// Mitsubishi GX Works2 project: MotionControl_JEC_FBs_Q   PLC: Q06UDV

TYPE stRemoteRegBasic : STRUCT
  bnRX : ARRAY [0..127] OF BOOL;
  bnRY : ARRAY [0..127] OF BOOL;
  unRWr : ARRAY [0..63] OF WORD;
  unRWw : ARRAY [0..63] OF WORD;
END_STRUCT END_TYPE

// global labels: Global1
VAR_GLOBAL
  Axis1 : AXIS_REF_JEC;
  G_stLinkBasic : stRemoteRegBasic;
  Axis2 : AXIS_REF_JEC;
END_VAR
// user libraries (not included): MotionControl_JEC_V100A

FUNCTION_BLOCK CCIEFBasicStart
VAR_IN_OUT
  Axis : AXIS_REF_JEC;  (* Axis information *)
END_VAR
VAR_INPUT
  Enable : BOOL;  (* Enable *)
END_VAR
VAR_OUTPUT
  Status : BOOL;  (* Normal completion *)
  Error : BOOL;  (* Error completion *)
  ErrorID : WORD;  (* Error code *)
END_VAR
VAR
  bEnablePls : BOOL;
  wAxisNo : INT;
  wRX3F : INT;
  wRY3F : INT;
END_VAR
(*****************************************************************************
 *    <FB NAME>		CCIEFBasicStart
 *   <Description>		CC-Link IEF Basic communication start
 *
 *   COPYRIGHT (C) 2016 MITSUBISHI ELECTRIC CORPORATION ALL RIGHT RESERVED  
 *****************************************************************************)

PLS(Enable, bEnablePls);
IF Enable THEN
	IF bEnablePls THEN
		Status	:= FALSE;
		Error		:= FALSE;
		ErrorID	:= 0;

		(* 入力ラベル範囲チェック *)
		wAxisNo := Axis.AxisNo;
		MOV(((wAxisNo < 1) OR ( 16 < wAxisNo)), H1100, ErrorID);

		IF (ErrorID = 0) THEN
			(* リンクデバイス算出 *)
			wRY3F	:= ((wAxisNo-1) * 64) + H003F;	(* RY(n+3)F:Basic通信指令 *)
			wRX3F	:= ((wAxisNo-1) * 64) + H003F;	(* RX(n+3)F:Basic通信準備完了 *)

			(* Basic通信指令セット *)
			SET(TRUE, G_stLinkBasic.bnRY[wRY3F]);
		END_IF;
	END_IF;
	
	(* 状態出力 *)
	IF (ErrorID = 0) THEN
		Status := G_stLinkBasic.bnRX[wRX3F];
	END_IF;

	Error := (ErrorID <> 0);

ELSE
	bEnablePls	:= FALSE;
	Status		:= FALSE;
	Error			:= FALSE;
	ErrorID		:= 0;
END_IF;
END_FUNCTION_BLOCK

PROGRAM PrgAxis1
VAR
  CCIEFBasicStart_1 : CCIEFBasicStart;
  PowerOn : BOOL;
  Homing : BOOL;
  ExecSpeed : BOOL;
  Velocity : LREAL;
  ExecTorque : BOOL;
  Torque : REAL;
  TorqueRamp : LREAL;
  ExecHalt : BOOL;
  ExecStop : BOOL;
  ReadError : BOOL;
  ExecReset : BOOL;
  ExecAbs : BOOL;
  Position : LREAL;
  ExecInc : BOOL;
  Distance : LREAL;
  ExecAdd : BOOL;
  Monitor : BOOL;
  MonPosition : LREAL;
  MonVelocity : LREAL;
  MonTorque : REAL;
  MC_Power_JEC_1 : MC_Power_JEC;
  MCv_Home_JEC_1 : MCv_Home_JEC;
  MC_MoveVelocity_JEC_1 : MC_MoveVelocity_JEC;
  MC_TorqueControl_JEC_1 : MC_TorqueControl_JEC;
  MC_Halt_JEC_1 : MC_Halt_JEC;
  MC_Stop_JEC_1 : MC_Stop_JEC;
  MC_ReadAxisError_JEC_1 : MC_ReadAxisError_JEC;
  MC_Reset_JEC_1 : MC_Reset_JEC;
  MC_MoveAbsolute_JEC_1 : MC_MoveAbsolute_JEC;
  MC_MoveRelative_JEC_1 : MC_MoveRelative_JEC;
  MC_MoveAdditive_JEC_1 : MC_MoveAdditive_JEC;
  MC_ReadActualPosition_JEC_1 : MC_ReadActualPosition_JEC;
  MC_ReadActualVelocity_JEC_1 : MC_ReadActualVelocity_JEC;
  MC_ReadActualTorque_JEC_1 : MC_ReadActualTorque_JEC;
  MC_ReadAxisInfo_JEC_1 : MC_ReadAxisInfo_JEC;
  MC_ReadStatus_JEC_1 : MC_ReadStatus_JEC;
  BasicStatus : BOOL;
  ErrorCode : WORD;
END_VAR
(* structured ladder/FBD written out as ST: instructions are called as NAME(EN, inputs, outputs); _pN, _eN, _tN stand for wires *)
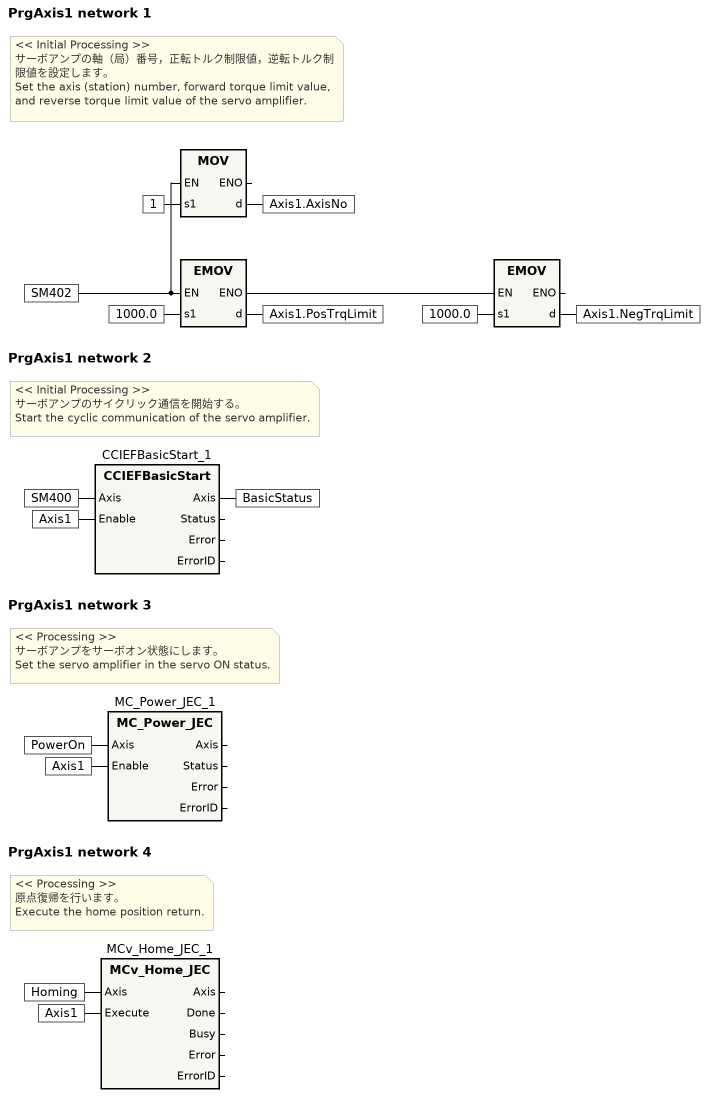
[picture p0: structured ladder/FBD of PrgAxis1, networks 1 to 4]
(* network 1 *)
(* << Initial Processing >> /  / サーボアンプの軸（局）番号，正転トルク制限値，逆転トルク制限値を設定します。 / Set the axis (station) number, forward torque limit value, and reverse torque limit value of the servo amplifier. *)
MOV(SM402, 1, Axis1.AxisNo);
_e1 := EMOV(SM402, 1000.0, Axis1.PosTrqLimit);
EMOV(_e1, 1000.0, Axis1.NegTrqLimit);
(* network 2 *)
(* << Initial Processing >> /  / サーボアンプのサイクリック通信を開始する。 / Start the cyclic communication of the servo amplifier. *)
CCIEFBasicStart_1(Axis := SM400, Enable := Axis1);
BasicStatus := CCIEFBasicStart_1.Axis;
(* network 3 *)
(* << Processing >> /  / サーボアンプをサーボオン状態にします。 / Set the servo amplifier in the servo ON status. *)
MC_Power_JEC_1(Axis := PowerOn, Enable := Axis1);
(* network 4 *)
(* << Processing >> /  / 原点復帰を行います。 / Execute the home position return. *)
MCv_Home_JEC_1(Axis := Homing, Execute := Axis1);
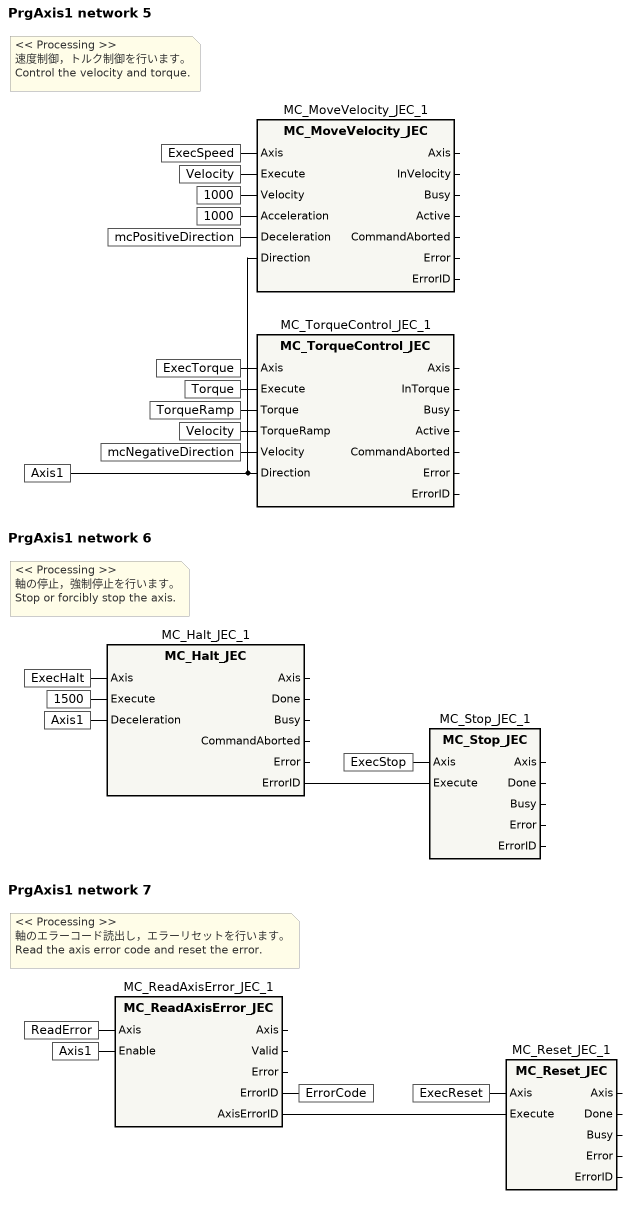
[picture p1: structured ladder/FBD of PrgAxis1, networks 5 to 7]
(* network 5 *)
(* << Processing >> /  / 速度制御，トルク制御を行います。 / Control the velocity and torque. *)
MC_MoveVelocity_JEC_1(Axis := ExecSpeed, Execute := Velocity, Velocity := 1000, Acceleration := 1000, Deceleration := mcPositiveDirection, Direction := Axis1);
MC_TorqueControl_JEC_1(Axis := ExecTorque, Execute := Torque, Torque := TorqueRamp, TorqueRamp := Velocity, Velocity := mcNegativeDirection, Direction := Axis1);
(* network 6 *)
(* << Processing >> /  / 軸の停止，強制停止を行います。 / Stop or forcibly stop the axis. *)
MC_Halt_JEC_1(Axis := ExecHalt, Execute := 1500, Deceleration := Axis1);
MC_Stop_JEC_1(Axis := ExecStop, Execute := MC_Halt_JEC_1.ErrorID);
(* network 7 *)
(* << Processing >> /  / 軸のエラーコード読出し，エラーリセットを行います。 / Read the axis error code and reset the error. *)
MC_ReadAxisError_JEC_1(Axis := ReadError, Enable := Axis1, ErrorID => ErrorCode);
MC_Reset_JEC_1(Axis := ExecReset, Execute := MC_ReadAxisError_JEC_1.AxisErrorID);
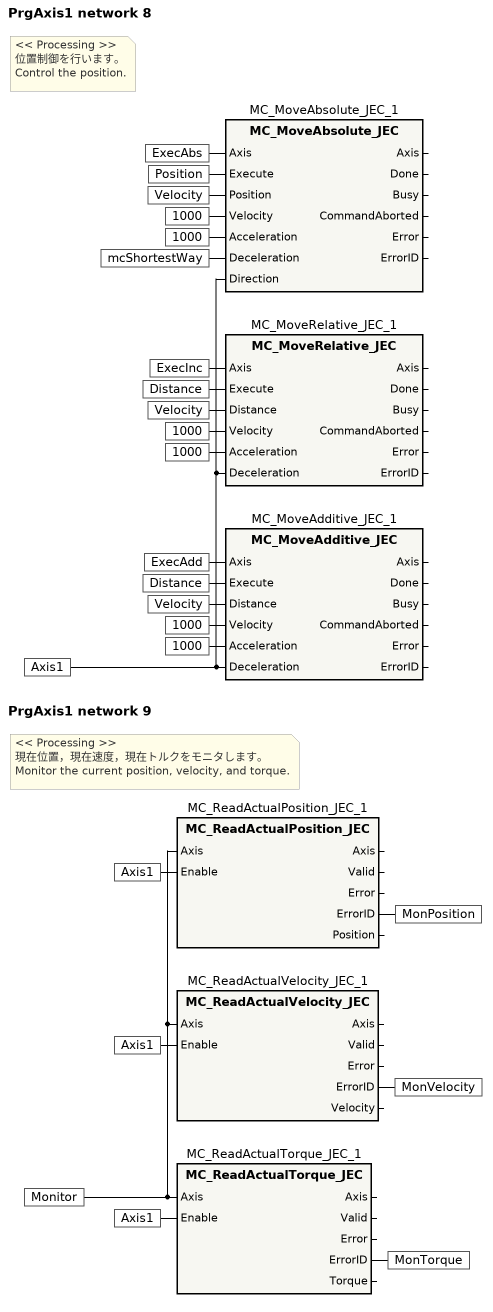
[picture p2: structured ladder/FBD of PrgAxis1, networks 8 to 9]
(* network 8 *)
(* << Processing >> /  / 位置制御を行います。 / Control the position. *)
MC_MoveAbsolute_JEC_1(Axis := ExecAbs, Execute := Position, Position := Velocity, Velocity := 1000, Acceleration := 1000, Deceleration := mcShortestWay, Direction := Axis1);
MC_MoveRelative_JEC_1(Axis := ExecInc, Execute := Distance, Distance := Velocity, Velocity := 1000, Acceleration := 1000, Deceleration := Axis1);
MC_MoveAdditive_JEC_1(Axis := ExecAdd, Execute := Distance, Distance := Velocity, Velocity := 1000, Acceleration := 1000, Deceleration := Axis1);
(* network 9 *)
(* << Processing >> /  / 現在位置，現在速度，現在トルクをモニタします。 / Monitor the current position, velocity, and torque. *)
MC_ReadActualPosition_JEC_1(Axis := Monitor, Enable := Axis1, ErrorID => MonPosition);
MC_ReadActualVelocity_JEC_1(Axis := Monitor, Enable := Axis1, ErrorID => MonVelocity);
MC_ReadActualTorque_JEC_1(Axis := Monitor, Enable := Axis1, ErrorID => MonTorque);
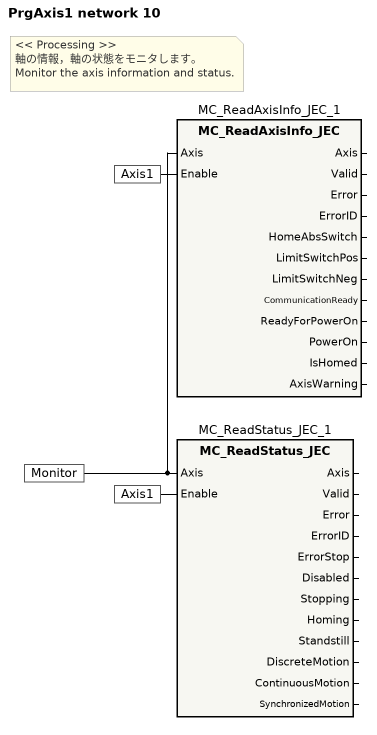
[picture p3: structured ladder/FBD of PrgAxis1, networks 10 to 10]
(* network 10 *)
(* << Processing >> /  / 軸の情報，軸の状態をモニタします。 / Monitor the axis information and status. *)
MC_ReadAxisInfo_JEC_1(Axis := Monitor, Enable := Axis1);
MC_ReadStatus_JEC_1(Axis := Monitor, Enable := Axis1);
END_PROGRAM

PROGRAM PrgAxis2
VAR
  CCIEFBasicStart_1 : CCIEFBasicStart;
  PowerOn : BOOL;
  Homing : BOOL;
  ExecSpeed : BOOL;
  Velocity : LREAL;
  ExecTorque : BOOL;
  Torque : REAL;
  TorqueRamp : LREAL;
  ExecHalt : BOOL;
  ExecStop : BOOL;
  ReadError : BOOL;
  ExecReset : BOOL;
  ExecAbs : BOOL;
  Position : LREAL;
  ExecInc : BOOL;
  Distance : LREAL;
  ExecAdd : BOOL;
  Monitor : BOOL;
  MonPosition : LREAL;
  MonVelocity : LREAL;
  MonTorque : REAL;
  MC_Power_JEC_1 : MC_Power_JEC;
  MCv_Home_JEC_1 : MCv_Home_JEC;
  MC_MoveVelocity_JEC_1 : MC_MoveVelocity_JEC;
  MC_TorqueControl_JEC_1 : MC_TorqueControl_JEC;
  MC_Halt_JEC_1 : MC_Halt_JEC;
  MC_Stop_JEC_1 : MC_Stop_JEC;
  MC_ReadAxisError_JEC_1 : MC_ReadAxisError_JEC;
  MC_Reset_JEC_1 : MC_Reset_JEC;
  MC_MoveAbsolute_JEC_1 : MC_MoveAbsolute_JEC;
  MC_MoveRelative_JEC_1 : MC_MoveRelative_JEC;
  MC_MoveAdditive_JEC_1 : MC_MoveAdditive_JEC;
  MC_ReadActualPosition_JEC_1 : MC_ReadActualPosition_JEC;
  MC_ReadActualVelocity_JEC_1 : MC_ReadActualVelocity_JEC;
  MC_ReadActualTorque_JEC_1 : MC_ReadActualTorque_JEC;
  MC_ReadAxisInfo_JEC_1 : MC_ReadAxisInfo_JEC;
  MC_ReadStatus_JEC_1 : MC_ReadStatus_JEC;
  BasicStatus : BOOL;
  ErrorCode : WORD;
END_VAR
(* structured ladder/FBD written out as ST: instructions are called as NAME(EN, inputs, outputs); _pN, _eN, _tN stand for wires *)
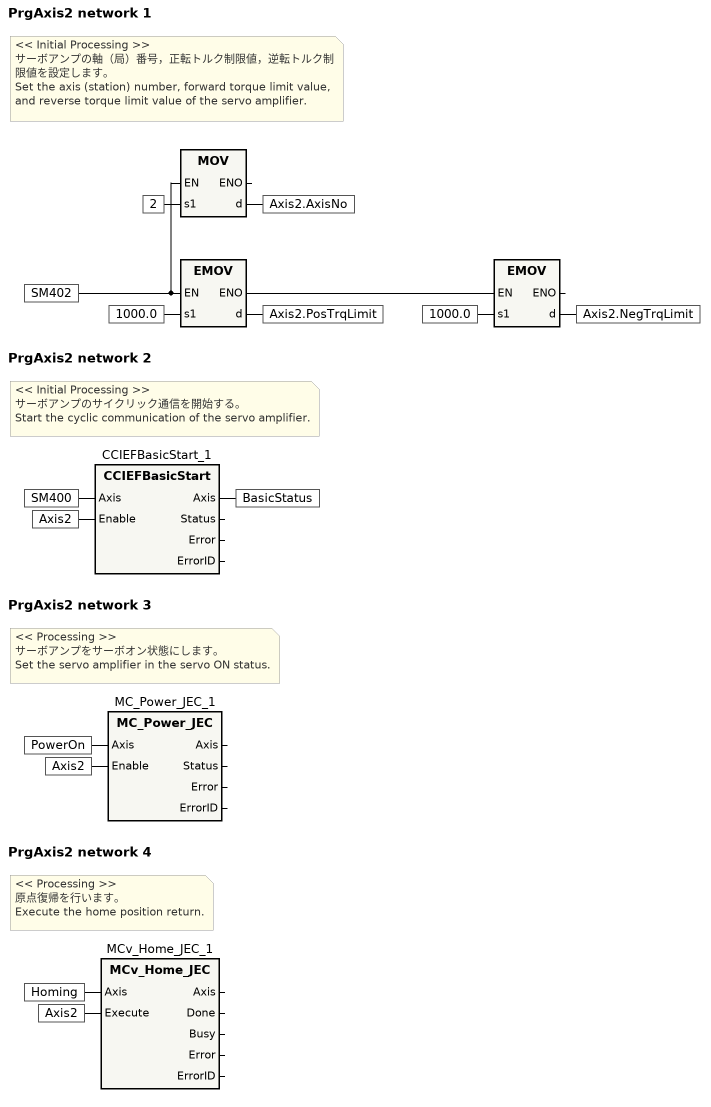
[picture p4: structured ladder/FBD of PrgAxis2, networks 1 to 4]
(* network 1 *)
(* << Initial Processing >> /  / サーボアンプの軸（局）番号，正転トルク制限値，逆転トルク制限値を設定します。 / Set the axis (station) number, forward torque limit value, and reverse torque limit value of the servo amplifier. *)
MOV(SM402, 2, Axis2.AxisNo);
_e1 := EMOV(SM402, 1000.0, Axis2.PosTrqLimit);
EMOV(_e1, 1000.0, Axis2.NegTrqLimit);
(* network 2 *)
(* << Initial Processing >> /  / サーボアンプのサイクリック通信を開始する。 / Start the cyclic communication of the servo amplifier. *)
CCIEFBasicStart_1(Axis := SM400, Enable := Axis2);
BasicStatus := CCIEFBasicStart_1.Axis;
(* network 3 *)
(* << Processing >> /  / サーボアンプをサーボオン状態にします。 / Set the servo amplifier in the servo ON status. *)
MC_Power_JEC_1(Axis := PowerOn, Enable := Axis2);
(* network 4 *)
(* << Processing >> /  / 原点復帰を行います。 / Execute the home position return. *)
MCv_Home_JEC_1(Axis := Homing, Execute := Axis2);
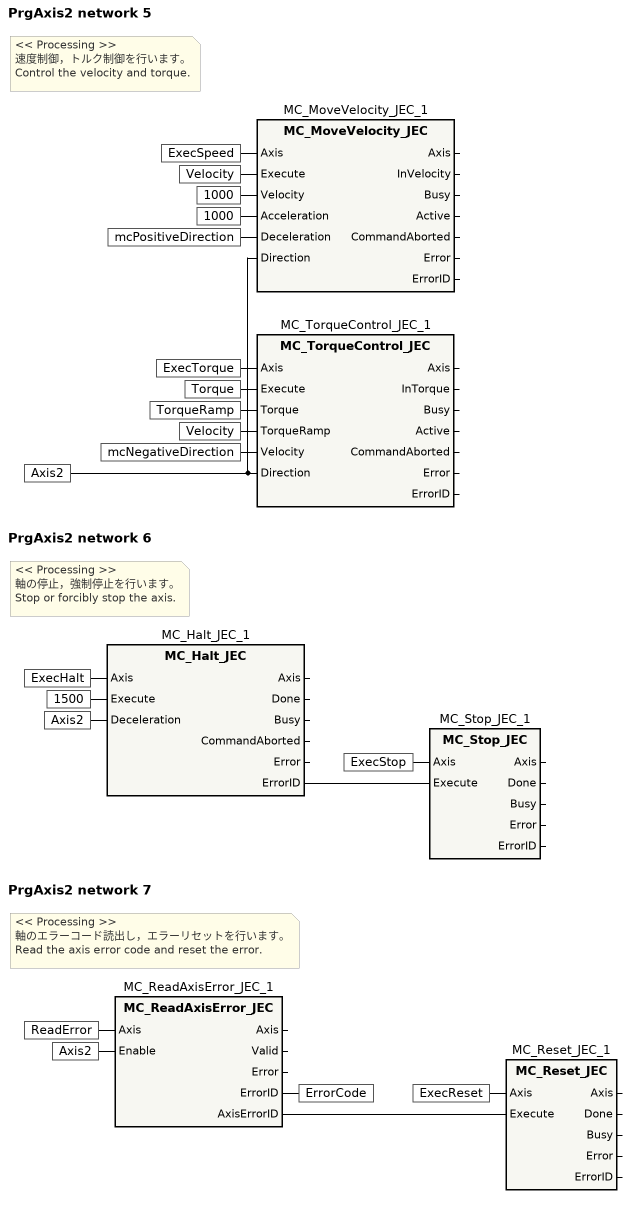
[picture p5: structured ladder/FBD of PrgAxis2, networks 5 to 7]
(* network 5 *)
(* << Processing >> /  / 速度制御，トルク制御を行います。 / Control the velocity and torque. *)
MC_MoveVelocity_JEC_1(Axis := ExecSpeed, Execute := Velocity, Velocity := 1000, Acceleration := 1000, Deceleration := mcPositiveDirection, Direction := Axis2);
MC_TorqueControl_JEC_1(Axis := ExecTorque, Execute := Torque, Torque := TorqueRamp, TorqueRamp := Velocity, Velocity := mcNegativeDirection, Direction := Axis2);
(* network 6 *)
(* << Processing >> /  / 軸の停止，強制停止を行います。 / Stop or forcibly stop the axis. *)
MC_Halt_JEC_1(Axis := ExecHalt, Execute := 1500, Deceleration := Axis2);
MC_Stop_JEC_1(Axis := ExecStop, Execute := MC_Halt_JEC_1.ErrorID);
(* network 7 *)
(* << Processing >> /  / 軸のエラーコード読出し，エラーリセットを行います。 / Read the axis error code and reset the error. *)
MC_ReadAxisError_JEC_1(Axis := ReadError, Enable := Axis2, ErrorID => ErrorCode);
MC_Reset_JEC_1(Axis := ExecReset, Execute := MC_ReadAxisError_JEC_1.AxisErrorID);
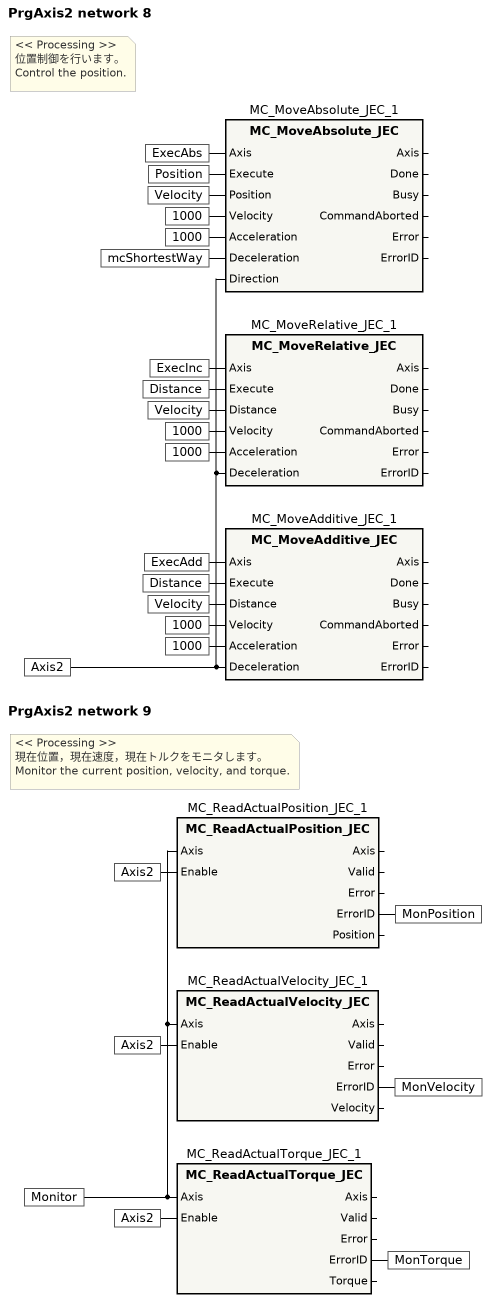
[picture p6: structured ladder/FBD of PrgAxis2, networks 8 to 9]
(* network 8 *)
(* << Processing >> /  / 位置制御を行います。 / Control the position. *)
MC_MoveAbsolute_JEC_1(Axis := ExecAbs, Execute := Position, Position := Velocity, Velocity := 1000, Acceleration := 1000, Deceleration := mcShortestWay, Direction := Axis2);
MC_MoveRelative_JEC_1(Axis := ExecInc, Execute := Distance, Distance := Velocity, Velocity := 1000, Acceleration := 1000, Deceleration := Axis2);
MC_MoveAdditive_JEC_1(Axis := ExecAdd, Execute := Distance, Distance := Velocity, Velocity := 1000, Acceleration := 1000, Deceleration := Axis2);
(* network 9 *)
(* << Processing >> /  / 現在位置，現在速度，現在トルクをモニタします。 / Monitor the current position, velocity, and torque. *)
MC_ReadActualPosition_JEC_1(Axis := Monitor, Enable := Axis2, ErrorID => MonPosition);
MC_ReadActualVelocity_JEC_1(Axis := Monitor, Enable := Axis2, ErrorID => MonVelocity);
MC_ReadActualTorque_JEC_1(Axis := Monitor, Enable := Axis2, ErrorID => MonTorque);
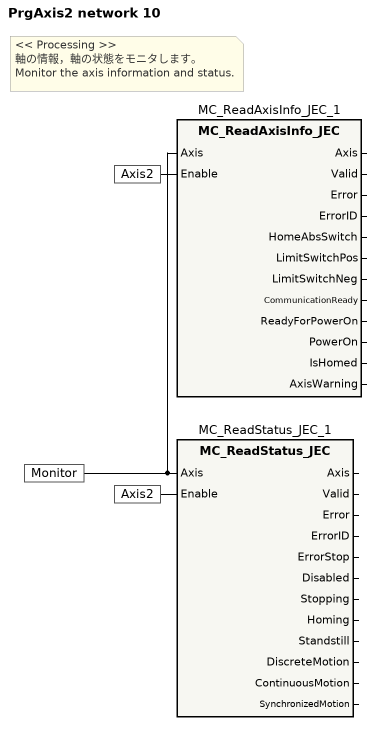
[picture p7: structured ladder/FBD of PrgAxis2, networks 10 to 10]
(* network 10 *)
(* << Processing >> /  / 軸の情報，軸の状態をモニタします。 / Monitor the axis information and status. *)
MC_ReadAxisInfo_JEC_1(Axis := Monitor, Enable := Axis2);
MC_ReadStatus_JEC_1(Axis := Monitor, Enable := Axis2);
END_PROGRAM
